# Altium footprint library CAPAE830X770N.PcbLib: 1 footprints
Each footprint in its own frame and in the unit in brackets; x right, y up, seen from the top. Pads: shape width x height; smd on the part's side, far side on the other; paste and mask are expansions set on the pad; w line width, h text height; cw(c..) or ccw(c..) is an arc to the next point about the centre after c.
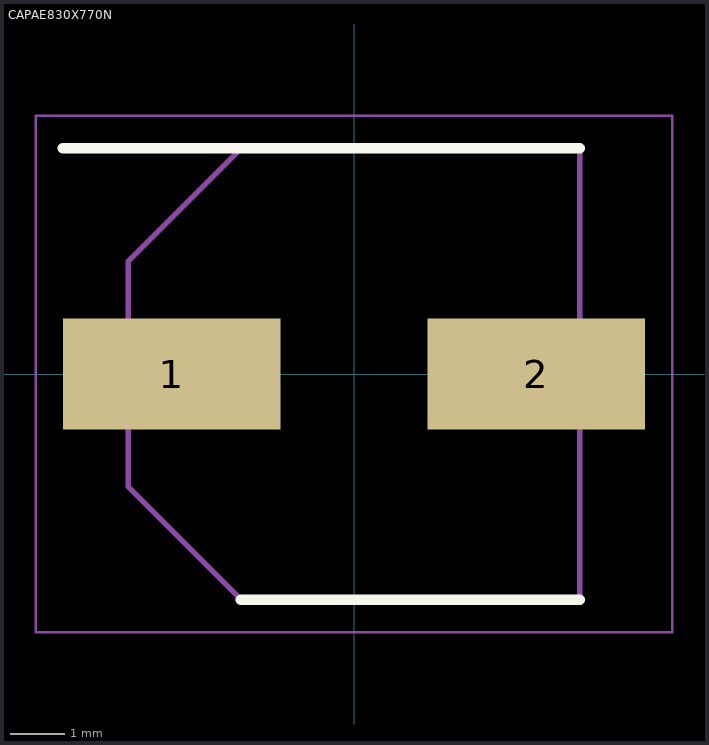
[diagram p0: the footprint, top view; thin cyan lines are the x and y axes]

## CAPAE830X770N [mm]
pads (2):
  rect 4x2.05 smd: 1(-3.35,0) 2(3.35,0)
Top Overlay:
  lines w0.2: -5.35,4.15 4.15,4.15 ; -2.075,-4.15 4.15,-4.15
Mechanical 15:
  lines w0.1: -4.15,-2.075 -4.15,2.075 -2.075,4.15 4.15,4.15 4.15,-4.15 -2.075,-4.15 -4.15,-2.075
Mechanical 20:
  lines w0.05: -5.85,-4.75 5.85,-4.75 5.85,4.75 -5.85,4.75 -5.85,-4.75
